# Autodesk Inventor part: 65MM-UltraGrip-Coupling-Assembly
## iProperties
Created: 2012-05
Part Number: 65MM-UltraGrip-Coupling-Assembly
Document SubType Name: Modeling
Designer: D Cole
Density: 1 g/cm^3
Author: D Cole
